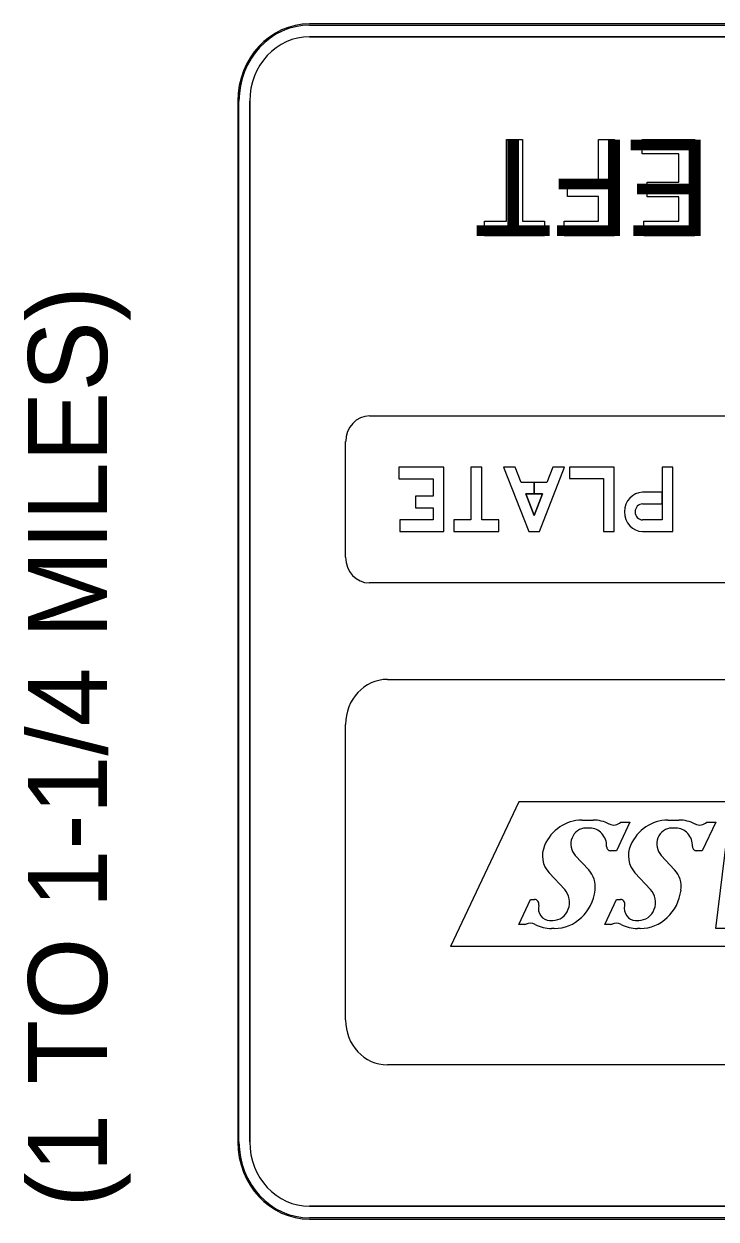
# Model space of a CAD drawing. Extents: x -102308 to -98250, y 54554 to 62383.
# Drawn here: x -101710 to -101409, y 61400 to 61919 of the extents above; entities that cross this region are included whole.
import ezdxf

# ---------------------------------------------------------------- set-up
doc = ezdxf.new("R2010")
doc.units = 0
for name, color, linetype in [('GSBWFill', 7, 'Continuous'), ('GSColorFill', 7, 'Continuous'), ('GSOutline', 7, 'Continuous'), ('SignPanel', 7, 'Continuous'), ('TextLabel', 7, 'Continuous')]:
    doc.layers.add(name, color=color, linetype=linetype)

msp = doc.modelspace()

# ---------------------------------------------------------------- linework, layer by layer
at = {"layer": 'GSBWFill'}
for p, q in [((-101133.26, 61919), (-101585.67, 61919)), ((-101585.67, 61913.42), (-101133.26, 61913.42)), ((-101616.88, 61885.49), (-101616.88, 61433.02)), ((-101611.68, 61433.02), (-101611.68, 61885.49)), ((-101133.21, 61405.09), (-101585.67, 61405.09)), ((-101585.67, 61399.51), (-101133.21, 61399.51))]:
    msp.add_line(p, q, dxfattribs=at)
for centre, major_axis, start_param, end_param in [((-101585.67, 61885.49), (0, -33.52), 3.141593, 4.712389), ((-101585.67, 61885.49), (0, -27.93), 3.141593, 4.712389), ((-101585.67, 61433.02), (0, -33.52), 4.712389, 6.283185), ((-101585.67, 61433.02), (0, -27.93), 4.712389, 6.283185)]:
    msp.add_ellipse(centre, major_axis=major_axis, ratio=0.931035, start_param=start_param, end_param=end_param, dxfattribs=at)
at = {"layer": 'GSColorFill'}
for p, q in [((-101133.21, 61919), (-101585.67, 61919)), ((-101616.88, 61885.49), (-101616.88, 61433.02)), ((-101585.67, 61399.51), (-101133.21, 61399.51))]:
    msp.add_line(p, q, dxfattribs=at)
for centre, start_param, end_param in [((-101585.67, 61885.49), 3.141593, 4.712389), ((-101585.67, 61433.02), 4.712389, 6.283185)]:
    msp.add_ellipse(centre, major_axis=(0, -33.52), ratio=0.931035, start_param=start_param, end_param=end_param, dxfattribs=at)
at = {"layer": 'GSOutline'}
for p, q in [((-101133.21, 61919), (-101585.67, 61919)), ((-101133.21, 61913.42), (-101585.67, 61913.42)), ((-101616.88, 61885.49), (-101616.88, 61433.02)), ((-101611.68, 61885.49), (-101611.68, 61433.02)), ((-101585.67, 61405.09), (-101133.21, 61405.09)), ((-101585.67, 61399.51), (-101133.21, 61399.51))]:
    msp.add_line(p, q, dxfattribs=at)
for centre, major_axis, start_param, end_param in [((-101585.67, 61885.49), (0, -33.52), 3.141593, 4.712389), ((-101585.67, 61885.49), (0, -27.93), 3.141593, 4.712389), ((-101585.67, 61433.02), (0, -33.52), 4.712389, 6.283185), ((-101585.67, 61433.02), (0, -27.93), 4.712389, 6.283185)]:
    msp.add_ellipse(centre, major_axis=major_axis, ratio=0.931035, start_param=start_param, end_param=end_param, dxfattribs=at)
at = {"layer": 'SignPanel'}
for p, q in [((-101133.26, 61919), (-101585.67, 61919)), ((-101133.21, 61919), (-101585.67, 61919)), ((-101585.67, 61918.45), (-101133.21, 61918.45)), ((-101585.67, 61913.42), (-101133.26, 61913.42)), ((-101616.88, 61885.49), (-101616.88, 61433.02)), ((-101616.88, 61885.49), (-101616.88, 61433.02)), ((-101616.36, 61433.02), (-101616.36, 61885.49)), ((-101611.68, 61433.02), (-101611.68, 61885.49)), ((-101559.62, 61748.63), (-101159.26, 61748.63)), ((-101570.02, 61687.19), (-101570.02, 61737.46)), ((-101432.38, 61715.4), (-101440.83, 61715.4)), ((-101432.38, 61703.39), (-101440.83, 61703.39)), ((-101432.38, 61703.39), (-101440.83, 61703.39)), ((-101432.38, 61703.39), (-101440.83, 61703.39)), ((-101159.26, 61676.01), (-101559.62, 61676.01)), ((-101551.82, 61634.08), (-101167.06, 61634.08)), ((-101570.02, 61486.09), (-101570.02, 61614.53)), ((-101494.59, 61580.81), (-101524.4, 61517.98)), ((-101334.71, 61580.81), (-101494.59, 61580.81)), ((-101467.27, 61572.96), (-101462.38, 61572.96)), ((-101446.33, 61572.08), (-101452.22, 61559.64)), ((-101450.28, 61572.08), (-101446.33, 61572.08)), ((-101429.9, 61572.96), (-101425.01, 61572.96)), ((-101408.95, 61572.08), (-101414.85, 61559.64)), ((-101412.9, 61572.08), (-101408.95, 61572.08)), ((-101463.77, 61569.46), (-101465.52, 61569.46)), ((-101426.39, 61569.46), (-101428.15, 61569.46)), ((-101408.97, 61525.83), (-101404.11, 61566)), ((-101470.12, 61557.55), (-101464.27, 61551.26)), ((-101452.22, 61559.64), (-101454.84, 61559.64)), ((-101432.74, 61557.55), (-101426.9, 61551.26)), ((-101414.85, 61559.64), (-101417.46, 61559.64)), ((-101474.71, 61542.73), (-101481.52, 61550.05)), ((-101437.34, 61542.73), (-101444.15, 61550.05)), ((-101494.67, 61527.58), (-101489.51, 61538.47)), ((-101489.51, 61538.47), (-101487.88, 61538.47)), ((-101457.31, 61527.58), (-101452.14, 61538.47)), ((-101452.14, 61538.47), (-101450.51, 61538.47)), ((-101481.27, 61529.33), (-101479.88, 61529.33)), ((-101443.9, 61529.33), (-101442.51, 61529.33)), ((-101492.23, 61527.58), (-101494.67, 61527.58)), ((-101479.22, 61525.83), (-101480.45, 61525.83)), ((-101454.87, 61527.58), (-101457.31, 61527.58)), ((-101441.84, 61525.83), (-101443.07, 61525.83)), ((-101403.13, 61525.83), (-101408.97, 61525.83)), ((-101339.02, 61517.98), (-101524.4, 61517.98)), ((-101167.06, 61466.54), (-101551.82, 61466.54)), ((-101133.21, 61405.09), (-101585.67, 61405.09)), ((-101133.21, 61400.07), (-101585.67, 61400.07)), ((-101585.67, 61399.51), (-101133.21, 61399.51)), ((-101585.67, 61399.51), (-101133.21, 61399.51))]:
    msp.add_line(p, q, dxfattribs=at)
for points in [[(-101500.07, 61833.3), (-101500.07, 61868.73), (-101493.06, 61868.73), (-101493.06, 61833.3), (-101483.54, 61833.3), (-101483.54, 61826.83), (-101509.62, 61826.83), (-101509.62, 61833.3), (-101500.07, 61833.3)], [(-101460.04, 61833.25), (-101460.04, 61843.94), (-101473.45, 61843.94), (-101473.45, 61850.45), (-101460.04, 61850.45), (-101460.04, 61868.73), (-101453.02, 61868.73), (-101453.02, 61826.83), (-101474.92, 61826.83), (-101474.92, 61833.25), (-101460.04, 61833.25)], [(-101418.04, 61868.73), (-101418.04, 61826.83), (-101440.36, 61826.83), (-101440.36, 61833.25), (-101425.05, 61833.25), (-101425.05, 61843.79), (-101438.89, 61843.79), (-101438.89, 61850.25), (-101425.05, 61850.25), (-101425.05, 61862.47), (-101440.95, 61862.47), (-101440.95, 61868.73), (-101418.04, 61868.73)], [(-101440.83, 61698.36), (-101427.7, 61698.36), (-101427.7, 61726.29), (-101432.38, 61726.29), (-101432.38, 61715.4)], [(-101440.83, 61698.36), (-101427.7, 61698.36), (-101427.7, 61726.29), (-101432.38, 61726.29), (-101432.38, 61703.39)], [(-101440.83, 61698.36), (-101427.7, 61698.36), (-101427.7, 61726.29), (-101432.38, 61726.29), (-101432.38, 61703.39)], [(-101440.83, 61710.37), (-101432.38, 61710.37), (-101432.38, 61715.4), (-101440.83, 61715.4)], [(-101440.83, 61710.37), (-101432.38, 61710.37), (-101432.38, 61715.4), (-101440.83, 61715.4)], [(-101440.83, 61710.37), (-101432.38, 61710.37), (-101432.38, 61703.39)]]:
    msp.add_lwpolyline(points, dxfattribs=at)
for points in [[(-101546.8, 61721.26), (-101531.97, 61721.26), (-101531.97, 61713.75), (-101539.65, 61713.75), (-101539.65, 61708.72), (-101531.97, 61708.72), (-101531.97, 61703.39), (-101546.41, 61703.39), (-101546.41, 61698.36), (-101527.29, 61698.36), (-101527.29, 61726.29), (-101546.8, 61726.29)], [(-101546.8, 61721.26), (-101531.97, 61721.26), (-101531.97, 61713.75), (-101539.65, 61713.75), (-101539.65, 61708.72), (-101531.97, 61708.72), (-101531.97, 61703.39), (-101546.41, 61703.39), (-101546.41, 61698.36), (-101527.29, 61698.36), (-101527.29, 61726.29), (-101546.8, 61726.29)], [(-101546.8, 61721.26), (-101531.97, 61721.26), (-101531.97, 61713.75), (-101539.65, 61713.75), (-101539.65, 61708.72), (-101531.97, 61708.72), (-101531.97, 61703.39), (-101546.41, 61703.39), (-101546.41, 61698.36), (-101527.29, 61698.36), (-101527.29, 61726.29), (-101546.8, 61726.29)], [(-101503.37, 61703.39), (-101510.78, 61703.39), (-101510.78, 61726.29), (-101515.46, 61726.29), (-101515.46, 61703.39), (-101522.87, 61703.39), (-101522.87, 61698.36), (-101503.37, 61698.36)], [(-101503.37, 61703.39), (-101510.78, 61703.39), (-101510.78, 61726.29), (-101515.46, 61726.29), (-101515.46, 61703.39), (-101522.87, 61703.39), (-101522.87, 61698.36), (-101503.37, 61698.36)], [(-101503.37, 61703.39), (-101510.78, 61703.39), (-101510.78, 61726.29), (-101515.46, 61726.29), (-101515.46, 61703.39), (-101522.87, 61703.39), (-101522.87, 61698.36), (-101503.37, 61698.36)], [(-101482.41, 61719.72), (-101493.65, 61719.72), (-101496.21, 61726.29), (-101501.29, 61726.29), (-101490.37, 61698.36), (-101485.69, 61698.36), (-101474.77, 61726.29), (-101479.84, 61726.29)], [(-101491.68, 61714.7), (-101488.03, 61714.7), (-101488.03, 61719.72), (-101493.65, 61719.72), (-101496.21, 61726.29), (-101501.29, 61726.29), (-101490.37, 61698.36), (-101485.69, 61698.36), (-101474.77, 61726.29), (-101479.84, 61726.29), (-101482.41, 61719.72), (-101488.03, 61719.72), (-101488.03, 61714.7), (-101484.38, 61714.7), (-101488.03, 61705.36)], [(-101491.68, 61714.7), (-101488.03, 61714.7), (-101488.03, 61719.72), (-101493.65, 61719.72), (-101496.21, 61726.29), (-101501.29, 61726.29), (-101490.37, 61698.36), (-101485.69, 61698.36), (-101474.77, 61726.29), (-101479.84, 61726.29), (-101482.41, 61719.72), (-101488.03, 61719.72), (-101488.03, 61714.7), (-101484.38, 61714.7), (-101488.03, 61705.36)], [(-101472.69, 61726.29), (-101472.69, 61721.4), (-101457.86, 61721.4), (-101457.86, 61698.36), (-101453.18, 61698.36), (-101453.18, 61726.29)], [(-101472.69, 61726.29), (-101472.69, 61721.4), (-101457.86, 61721.4), (-101457.86, 61698.36), (-101453.18, 61698.36), (-101453.18, 61726.29)], [(-101472.69, 61726.29), (-101472.69, 61721.4), (-101457.86, 61721.4), (-101457.86, 61698.36), (-101453.18, 61698.36), (-101453.18, 61726.29)], [(-101491.68, 61714.7), (-101488.03, 61705.36), (-101484.38, 61714.7)]]:
    msp.add_lwpolyline(points, close=True, dxfattribs=at)
for centre, major_axis, start_param, end_param in [((-101585.67, 61885.49), (0, -33.52), 3.141593, 4.712389), ((-101585.67, 61885.49), (0, -33.52), 3.141593, 4.712389), ((-101585.67, 61885.49), (0, -32.96), 3.141593, 4.712389), ((-101585.67, 61885.49), (0, -27.93), 3.141593, 4.712389), ((-101559.52, 61737.46), (0, 11.17), 0, 1.570796), ((-101440.83, 61706.88), (0, -8.52), 3.141593, 6.283185), ((-101440.83, 61706.88), (0, -8.52), 3.141593, 6.283185), ((-101440.83, 61706.88), (0, -8.52), 3.141593, 6.283185), ((-101440.83, 61706.88), (0, -3.49), 3.141593, 6.283185), ((-101440.83, 61706.88), (0, -3.49), 3.141593, 6.283185), ((-101440.83, 61706.88), (0, -3.49), 3.141593, 6.283185), ((-101559.62, 61687.19), (0, -11.17), 4.712389, 6.283185), ((-101551.82, 61614.53), (0, 19.55), 0, 1.570796), ((-101467.27, 61553.76), (0, 19.2), 0, 1.133591), ((-101462.38, 61555.5), (0, 17.45), 5.836023, 6.283185), ((-101453.38, 61575.65), (0, 4.89), 2.69443, 3.895387), ((-101429.89, 61553.76), (0, 19.2), 0, 1.133591), ((-101425, 61555.5), (0, 17.45), 5.836023, 6.283185), ((-101416.01, 61575.65), (0, 4.89), 2.69443, 3.895387), ((-101465.52, 61562.49), (0, 6.98), 0, 2.356194), ((-101463.77, 61561.61), (0, -7.85), 1.547521, 3.141593), ((-101428.15, 61562.49), (0, 6.98), 0, 2.356194), ((-101426.4, 61561.61), (0, -7.85), 1.547521, 3.141593), ((-101474.63, 61557.45), (0, 10.47), 1.133591, 2.356194), ((-101454.83, 61561.39), (0, -1.75), 4.689114, 6.283185), ((-101437.25, 61557.45), (0, 10.47), 1.133591, 2.356194), ((-101417.46, 61561.39), (0, -1.75), 4.689114, 6.283185), ((-101471.16, 61543.87), (0, -10.47), 1.436562, 2.356194), ((-101433.79, 61543.87), (0, -10.47), 1.436562, 2.356194), ((-101479.88, 61537.18), (0, 7.85), 3.141593, 5.497787), ((-101479.21, 61545.03), (0, -19.2), 6.283185, 7.719747), ((-101442.51, 61537.18), (0, 7.85), 3.141593, 5.497787), ((-101441.84, 61545.03), (0, -19.2), 6.283185, 7.719747), ((-101487.88, 61536.37), (0, 2.09), 4.462658, 6.283185), ((-101481.27, 61534.56), (0, 5.24), 1.321066, 3.141593), ((-101450.51, 61536.37), (0, 2.09), 4.462658, 6.283185), ((-101443.9, 61534.56), (0, 5.24), 1.321066, 3.141593), ((-101492.24, 61529.68), (0, -2.09), 0, 0.384579), ((-101489.68, 61522.88), (0, -5.24), 2.68937, 3.526171), ((-101480.45, 61543.29), (0, -17.45), 5.830963, 6.283185), ((-101454.86, 61529.68), (0, -2.09), 0, 0.384579), ((-101452.3, 61522.88), (0, -5.24), 2.68937, 3.526171), ((-101443.07, 61543.29), (0, -17.45), 5.830963, 6.283185), ((-101551.82, 61486.09), (0, -19.55), 4.712389, 6.283185), ((-101585.67, 61433.02), (0, -33.52), 4.712389, 6.283185), ((-101585.67, 61433.02), (0, -33.52), 4.712389, 6.283185), ((-101585.67, 61433.02), (0, -32.96), 4.712389, 6.283185), ((-101585.67, 61433.02), (0, -27.93), 4.712389, 6.283185)]:
    msp.add_ellipse(centre, major_axis=major_axis, ratio=0.931035, start_param=start_param, end_param=end_param, dxfattribs=at)

# ---------------------------------------------------------------- texts
for s, p in [('T', (-101480.02, 61868.73)), ('T', (-101480.02, 61868.73)), ('F', (-101446.01, 61868.73)), ('F', (-101446.01, 61868.73)), ('E', (-101411.02, 61868.73)), ('E', (-101411.02, 61868.73))]:
    msp.add_text(s, height=41.89, rotation=180, dxfattribs=at).set_placement(p)
at = {"layer": 'TextLabel'}
msp.add_text('(1 TO 1-1/4 MILES)', height=34.335, rotation=90, dxfattribs=at).set_placement((-101673.74, 61404.5))

doc.saveas('drawing.dxf')
